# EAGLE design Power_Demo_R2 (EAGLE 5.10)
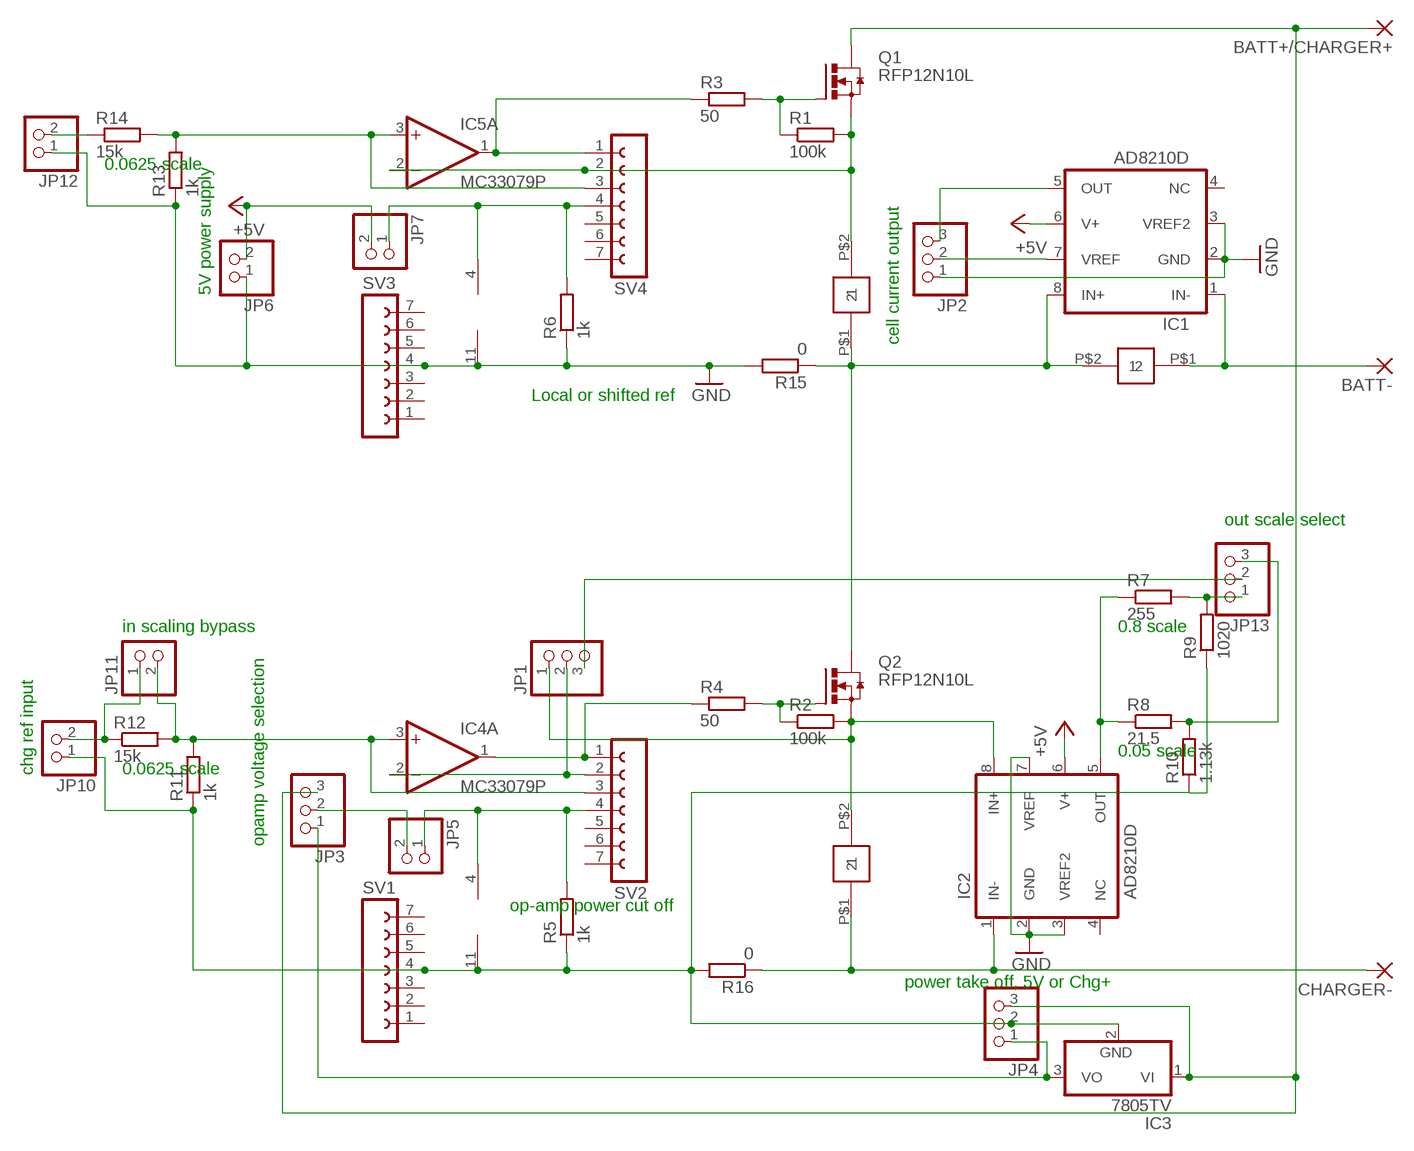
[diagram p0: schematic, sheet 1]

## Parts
BATT+/CHARGER+  3,81/1,4  [3,81/1,4]
BATT-  3,81/1,4  [3,81/1,4]
CHARGER-  3,81/1,4  [3,81/1,4]
IC1  AD8210D  [SO08]
IC2  AD8210D  [SO08]
IC3  7805TV  [TO220V]
IC4  MC33079P  [DIL14]
IC5  MC33079P  [DIL14]
JP1  PINHD-1X3  [1X03]
JP2  PINHD-1X3  [1X03]
JP3  PINHD-1X3  [1X03]
JP4  PINHD-1X3  [1X03]
JP5  PINHD-1X2  [1X02]
JP6  PINHD-1X2  [1X02]
JP7  PINHD-1X2  [1X02]
JP10  PINHD-1X2  [1X02]
JP11  PINHD-1X2  [1X02]
JP12  PINHD-1X2  [1X02]
JP13  PINHD-1X3  [1X03]
Q1  RFP12N10L  [TO220-W/657-20ABP]
Q2  RFP12N10L  [TO220-W/657-20ABP]
R1  100k  R-EU_R0805  [R0805]
R2  100k  R-EU_R0805  [R0805]
R3  50  R-EU_R0805  [R0805]
R4  50  R-EU_R0805  [R0805]
R5  1k  R-EU_R0805  [R0805]
R6  1k  R-EU_R0805  [R0805]
R7  255  R-EU_R0805  [R0805]
R8  21.5  R-EU_R0805  [R0805]
R9  1020  R-EU_R0805  [R0805]
R10  1.13k  R-EU_R0805  [R0805]
R11  1k  R-EU_R0805  [R0805]
R12  15k  R-EU_R0805  [R0805]
R13  1k  R-EU_R0805  [R0805]
R14  15k  R-EU_R0805  [R0805]
R15  0  R-EU_R0805  [R0805]
R16  0  R-EU_R0805  [R0805]
SV1  FE07-1  [FE07]
SV2  FE07-1  [FE07]
SV3  FE07-1  [FE07]
SV4  FE07-1  [FE07]
U$1  630HR050E  [630HR050E]
U$2  630HR050E  [630HR050E]
U$3  630HR050E  [630HR050E]

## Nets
+5V: IC1.6(V+) IC2.6(V+) JP6.2 JP7.2
GND: IC1.2(GND) IC1.3(VREF2) IC2.2(GND) IC2.3(VREF2) IC2.7(VREF) IC5.11(P:V-) JP2.1 JP6.1 JP12.1 R6.1 R13.1 R15.2 SV3.4
LOAD: BATT+/CHARGER+.1(P) IC3.1(VI) JP3.3 JP4.3 Q1.2(D)
N$1: IC1.8(IN+) Q2.2(D) R15.1 U$1.P$1 U$2.P$2
N$2: IC3.3(VO) JP3.1 JP4.1
N$3: IC2.8(IN+) JP1.1 Q2.3(S) R2.2 U$3.P$2
N$4: IC1.5(OUT) JP2.3
N$5: BATT-.1(P) IC1.1(IN-) U$2.P$1
N$6: Q2.1(G) R2.1 R4.2
N$8: Q1.1(G) R1.1 R3.2
N$9: IC1.7(VREF) JP2.2
N$10: JP1.3 JP13.2
N$11: CHARGER-.1(P) IC2.1(IN-) R16.1 U$3.P$1
N$12: IC4.4(P:V+) JP5.1 R5.2 SV2.4
N$13: IC4.1(A:OUT) R4.1 SV2.1
N$14: IC4.2(A:-IN) JP1.2 SV2.2
N$15: JP13.1 R7.2 R9.2
N$17: JP10.2 JP11.1 R12.1
N$18: JP3.2 JP5.2
N$19: IC4.3(A:+IN) JP11.2 R11.2 R12.2 SV2.3
N$20: IC5.1(A:OUT) R3.1 SV4.1
N$21: IC5.2(A:-IN) Q1.3(S) R1.2 SV4.2 U$1.P$2
N$22: IC2.5(OUT) R7.1 R8.1
N$23: JP13.3 R8.2 R10.2
N$24: IC5.4(P:V+) JP7.1 R6.2 SV4.4
N$27: JP12.2 R14.1
N$28: IC5.3(A:+IN) R13.2 R14.2 SV4.3
N$29: IC3.2(GND) IC4.11(P:V-) JP4.2 JP10.1 R5.1 R9.1 R10.1 R11.1 R16.2 SV1.4
Unconnected: IC4.5(B:+IN) IC4.6(B:-IN) IC4.7(B:OUT) IC4.8(C:OUT) IC4.9(C:-IN) IC4.10(C:+IN) IC4.12(D:+IN) IC4.13(D:-IN) IC4.14(D:OUT) IC5.5(B:+IN) IC5.6(B:-IN) IC5.7(B:OUT) IC5.8(C:OUT) IC5.9(C:-IN) IC5.10(C:+IN) IC5.12(D:+IN) IC5.13(D:-IN) IC5.14(D:OUT) SV1.1 SV1.2 SV1.3 SV1.5 SV1.6 SV1.7 SV2.5 SV2.6 SV2.7 SV3.1 SV3.2 SV3.3 SV3.5 SV3.6 SV3.7 SV4.5 SV4.6 SV4.7

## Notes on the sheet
- 0.0625 scale
- cell current output
- 5V power supply
- Local or shifted ref
- out scale select
- in scaling bypass | 0.8 scale
- 0.05 scale
- chg ref input | 0.0625 scale
- opamp voltage selection
- op-amp power cut off
- power take off, 5V or Chg+

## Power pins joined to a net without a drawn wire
NC: IC1.4(NC) IC2.4(NC)

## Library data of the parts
BATT+/CHARGER+ BATT- CHARGER- = wirepad:3,81/1,4: THROUGH-HOLE PAD
IC1 IC2 = NEWPARTS:AD8210: High Voltage, Bidirectional Current Shunt Monitor
IC3 = linear:78*: Positive VOLTAGE REGULATOR Source: http://cache.national.com/ds/LM/LM78L05.pdf http://www.fairchildsemi.com/ds/LM/LM7805.pdf
IC4 IC5 = linear:MC33079: OP AMP
JP1-JP4 JP13 = pinhead:PINHD-1X3: PIN HEADER
JP5-JP7 JP10-JP12 = pinhead:PINHD-1X2: PIN HEADER
Q1 Q2 = NEWPARTS:RFP12N10L: N-Channel Power MOSFET 100V; 12A; 0,2Ohm< Logic Level
R1-R16 = rcl:R-EU_: RESISTOR, European symbol
SV1-SV4 = con-lsta:FE07-1: FEMALE HEADER
U$1-U$3 = NEWPARTS:630HR050E

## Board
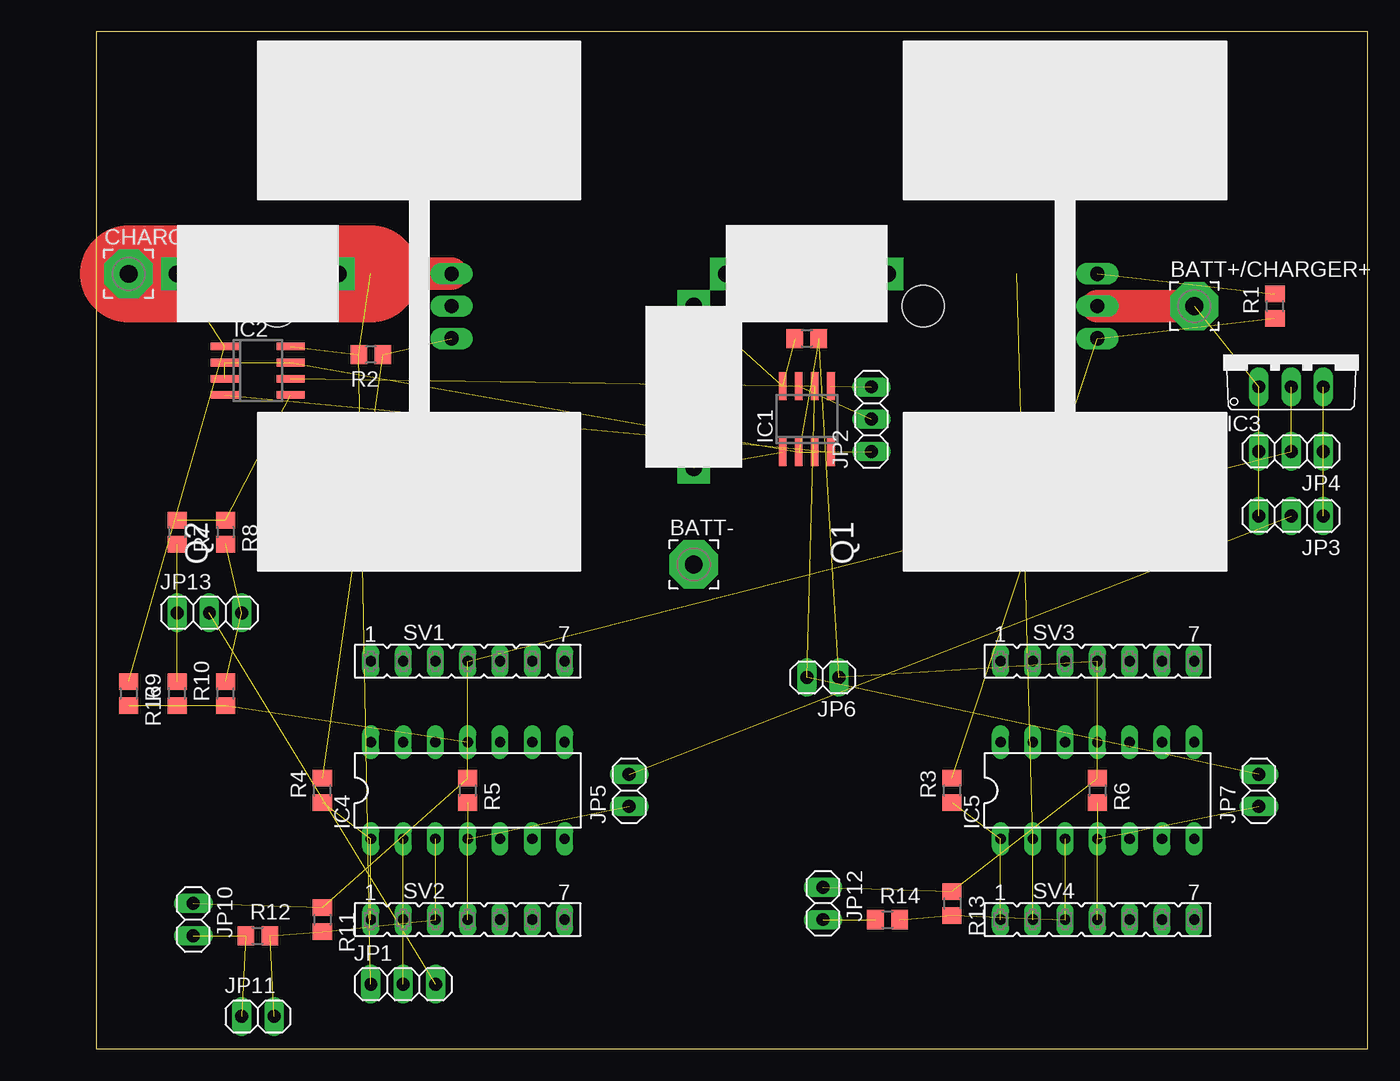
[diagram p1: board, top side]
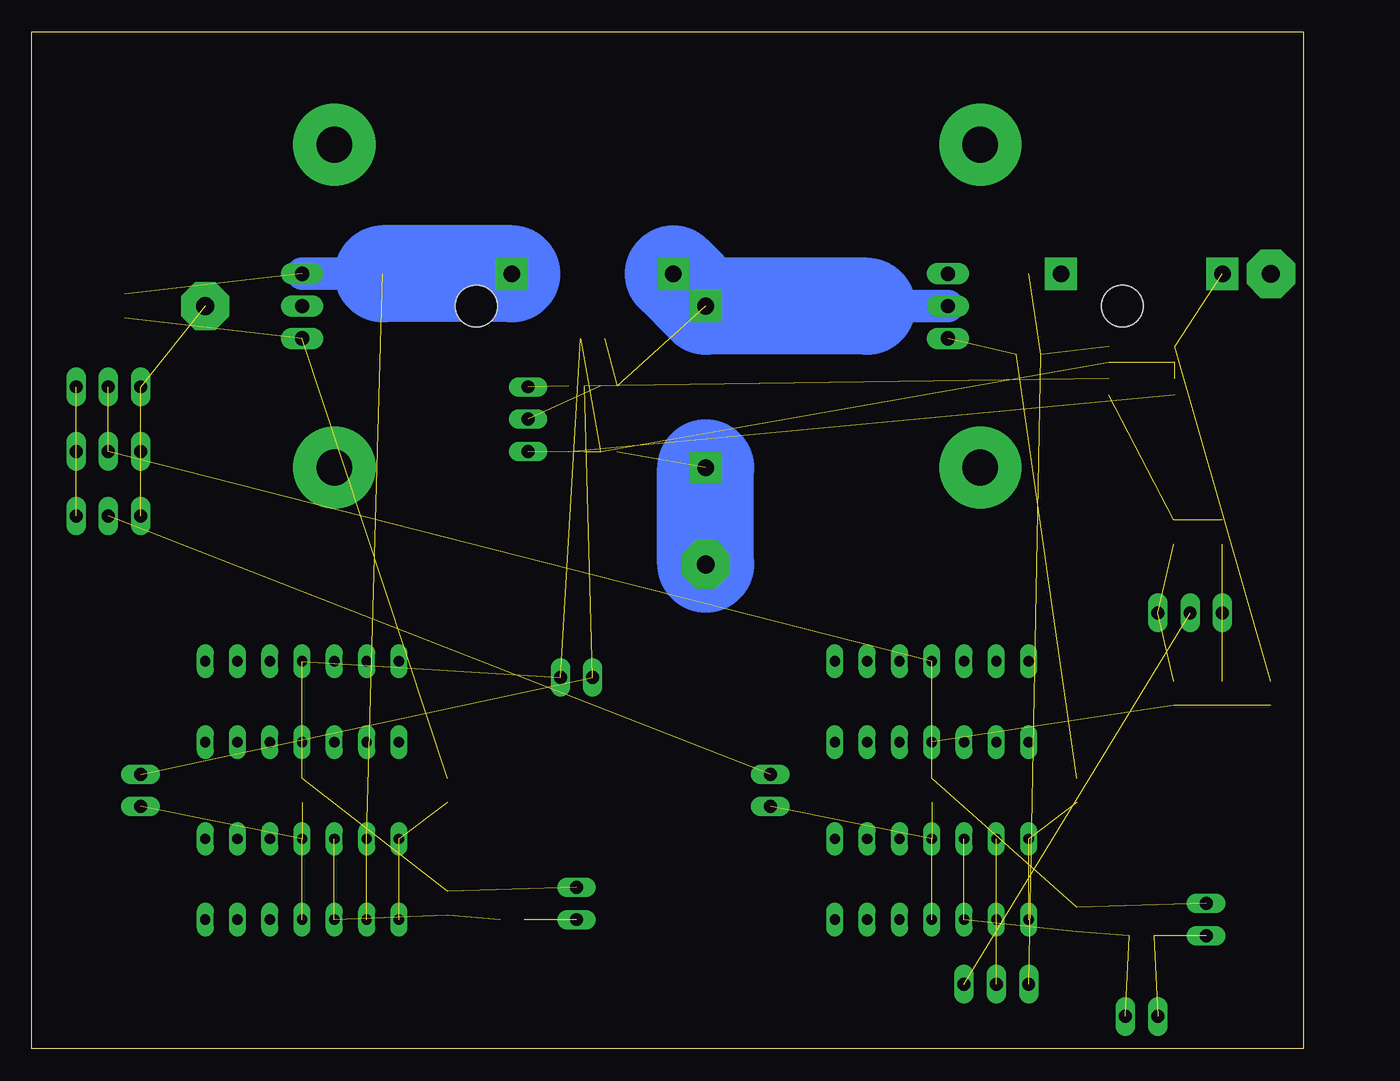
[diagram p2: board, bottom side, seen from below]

Size 100 x 80 mm. Coordinates in mm from the lower left corner, seen from the top.
Outline: 0,0 100,0 100,80 0,80 0,0
Copper layers (1*16): Top 0.035mm / dielectric 1.5mm / Bottom 0.035mm
Design rules "default": minimum track width 10mil, minimum drill 24mil, track to track 8mil, track to pad 8mil, pad to pad 8mil, via to via 8mil, smd to smd 8mil, copper to edge 40mil, drill to drill 8mil, minimum pad ring 10mil, minimum via ring 8mil, stop-mask expansion 4mil, vias tented up to drill 0mil, thermal gap 10mil

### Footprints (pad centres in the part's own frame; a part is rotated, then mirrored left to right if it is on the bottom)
3,81/1,4 = drill 1.397 pad 3.81 octagon: 1 0,0
SO08 = smd 0.6 x 2.2: 1 -1.905,-2.6; 2 -0.635,-2.6; 3 0.635,-2.6; 4 1.905,-2.6; 5 1.905,2.6; 6 0.635,2.6; 7 -0.635,2.6; 8 -1.905,2.6
TO220V = drill 1.016 long: 1 -2.54,-2.54; 2 0,-2.54; 3 2.54,-2.54
DIL14 = drill 0.813 long: 1 -7.62,-3.81; 2 -5.08,-3.81; 3 -2.54,-3.81; 4 0,-3.81; 5 2.54,-3.81; 6 5.08,-3.81; 7 7.62,-3.81; 8 7.62,3.81; 9 5.08,3.81; 10 2.54,3.81; 11 0,3.81; 12 -2.54,3.81; 13 -5.08,3.81; 14 -7.62,3.81
1X03 = drill 1.016 long: 1 -2.54,0; 2 0,0; 3 2.54,0
1X02 = drill 1.016 long: 1 -1.27,0; 2 1.27,0
TO220-W/657-20ABP = drill 1.118 long: 1 -2.54,-2.54; 2 0,-2.54; 3 2.54,-2.54 | drill 2.8 pad 6.452 round: P$1 -12.7,0; P$2 12.7,0 | hole 3.302: 0,11.176
R0805 = smd 1.3 x 1.5: 1 -0.95,0; 2 0.95,0
FE07 = drill 0.813 long: 1 -7.62,0; 2 -5.08,0; 3 -2.54,0; 4 0,0; 5 2.54,0; 6 5.08,0; 7 7.62,0
630HR050E = drill 1.3 pad 2.54 square: P$1 -6.35,0; P$2 6.35,0

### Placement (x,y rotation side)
BATT+/CHARGER+  86.36,58.42 0 top
BATT-  46.99,38.1 0 top
CHARGER-  2.54,60.96 0 top
IC1  55.88,49.53 0 top
IC2  12.7,53.34 270 top
IC3  93.98,54.61 0 top
IC4  29.21,20.32 0 top
IC5  78.74,20.32 0 top
JP1  24.13,5.08 0 top
JP2  60.96,49.53 90 top
JP3  93.98,41.91 180 top
JP4  93.98,46.99 180 top
JP5  41.91,20.32 90 top
JP6  57.15,29.21 180 top
JP7  91.44,20.32 90 top
JP10  7.62,10.16 270 top
JP11  12.7,2.54 0 top
JP12  57.15,11.43 270 top
JP13  8.89,34.29 0 top
Q1  76.2,58.42 90 top
Q2  25.4,58.42 90 top
R1  92.71,58.42 90 top
R2  21.59,54.61 180 top
R3  67.31,20.32 90 top
R4  17.78,20.32 90 top
R5  29.21,20.32 270 top
R6  78.74,20.32 270 top
R7  6.35,40.64 270 top
R8  10.16,40.64 270 top
R9  6.35,27.94 90 top
R10  10.16,27.94 90 top
R11  17.78,10.16 270 top
R12  12.7,8.89 0 top
R13  67.31,11.43 270 top
R14  62.23,10.16 0 top
R15  55.88,55.88 0 top
R16  2.54,27.94 270 top
SV1  29.21,30.48 0 top
SV2  29.21,10.16 0 top
SV3  78.74,30.48 0 top
SV4  78.74,10.16 0 top
U$1  55.88,60.96 0 top
U$2  46.99,52.07 90 top
U$3  12.7,60.96 0 top

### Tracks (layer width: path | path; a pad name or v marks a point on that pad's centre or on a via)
+5V  (3 unrouted)
GND  (12 unrouted)
LOAD  (3 unrouted)
  Top 2.54: Q1.2 BATT+/CHARGER+.1
N$1  (2 unrouted)
  Bottom 2.54: Q2.2 34.29,58.42
  Bottom 7.62: U$1.P$1 U$2.P$2 34.29,58.42
N$2  (2 unrouted)
N$3  (3 unrouted)
  Top 2.54: 21.59,60.96 Q2.3
  Top 7.62: U$3.P$2 21.59,60.96
N$4  (1 unrouted)
N$5  (1 unrouted)
  Bottom 7.62: BATT-.1 U$2.P$1
N$6  (2 unrouted)
N$8  (2 unrouted)
N$9  (1 unrouted)
N$10  (1 unrouted)
N$11  (2 unrouted)
  Top 7.62: CHARGER-.1 U$3.P$1
N$12  (3 unrouted)
N$13  (2 unrouted)
N$14  (2 unrouted)
N$15  (2 unrouted)
N$17  (2 unrouted)
N$18  (1 unrouted)
N$19  (4 unrouted)
N$20  (2 unrouted)
N$21  (3 unrouted)
  Bottom 2.54: 72.39,60.96 Q1.3
  Bottom 7.62: U$1.P$2 72.39,60.96
N$22  (2 unrouted)
N$23  (2 unrouted)
N$24  (3 unrouted)
N$27  (1 unrouted)
N$28  (3 unrouted)
N$29  (9 unrouted)
NC  (1 unrouted)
